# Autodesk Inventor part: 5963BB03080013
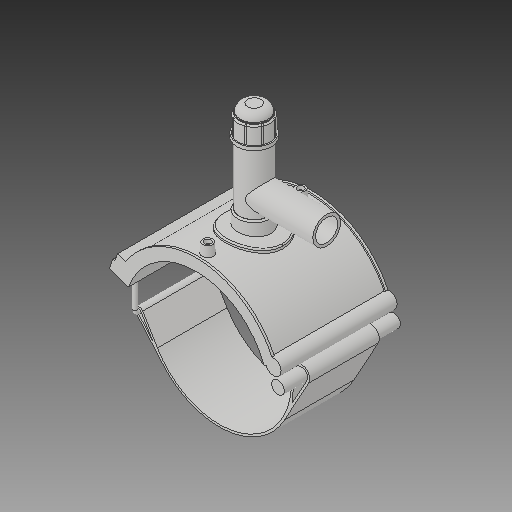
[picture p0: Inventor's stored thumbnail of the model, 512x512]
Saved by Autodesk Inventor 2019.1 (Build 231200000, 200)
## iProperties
Created: 2017-07
Part Number: 5963BB03080013
Material: Generic
Description: PLASSON TAPPING SADDLE 8''IPS x 1 1/4''IPS
Document SubType Name: Modeling
Designer: KIM
Mass: 1712.7 g
Surface Area: 2671.49 cm^2
Volume: 1712.7 cm^3
Density: 1 g/cm^3
Appearance: Default
Author: KIM
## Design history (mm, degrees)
derived "5963B.ipt"
feature "Solid1::5963B.ipt"
feature "Solid2::5963B.ipt"
feature "Solid4::5963B.ipt"
feature "Solid5::5963B.ipt"
tag "TaggingFeature1" dims "d0" = 218.7
body "Solid1"
body "Solid2"
other parameters: "d2" = 269.748, "d3" = 54.675, "d4" = 176.022, "d5" = 0, "d6" = 0.1, "d8" = 0, "d19" = 6, "d20" = 6, "d21" = 105.6132, "d23" = 0, "d24" = 52.8066, "d26" = 0, "d29" = 3, "d30" = 72.9, "d31" = 6, "d32" = 0, "d33" = 0, "d34" = 0.6, "d40" = 129.64536, "d41" = 87.48, "d43" = 0, "d45" = 0, "d47" = 230.2722, "d70" = 15, "d72" = 0, "d73" = 6, "d75" = 5, "d76" = 0, "d77" = 10.935, "d78" = 139.35, "d79" = 15, "d80" = 70.4088, "d82" = 5 deg, "d84" = 4, "d85" = 14, "d86" = 0, "d87" = 3, "d88" = 0, "d89" = 1, "d90" = 1, "d91" = 140.8176, "d92" = 0, "d93" = 0.5, "d94" = 115.10526, "d96" = 254.30436, "d97" = 3.52044, "d98" = 0, "d102" = 2.187, "d120" = 140 deg, "d121" = 24.228, "d122" = 20 deg, "d123" = 498.636, "d124" = 149.5908, "d126" = 0, "d143" = 225.261, "d145" = 23.55231, "d149" = 3.2805, "d150" = 25.90754, "d153" = 176.022, "d154" = 0, "d156" = 124.659, "d157" = 160 deg, "d159" = 6.1236, "d161" = 3.2805, "d162" = 105.6132, "d163" = 0, "d164" = 109.35, "d167" = 21.87, "d168" = 121.61854, "d170" = 3.2805, "d172" = 0, "d173" = 1, "d175" = 109.35, "d176" = 20 deg, "d177" = 15.309, "d178" = 30.618, "d180" = 0, "d183" = 12.2472, "d184" = 12.2472, "d185" = 57.20715, "d186" = 57.20715, "d187" = 124.659, "d188" = 9.1854, "d189" = 15.309, "d190" = 0, "d191" = 186.9885, "d193" = 6.1236, "d194" = 6.16077, "d195" = 90 deg, "d197" = 0, "d199" = 0, "d200" = 15.309, "d202" = 0, "d203" = 177.038, "d204" = 49.8636, "d205" = 36.7416, "d206" = 44.6148, "d207" = 132.7785, "d208" = 138.08964, "d209" = 164.64534, "d210" = 45.13968, "d211" = 52.488, "d212" = 41.9904, "d213" = 39.5766, "d216" = 0, "d217" = 21.87, "d218" = 10.935, "d219" = 2.187, "d222" = 218.7, "d224" = 0, "d230" = 2.187, "d233" = 6, "d236" = 89.916, "d237" = 52.8066, "d238" = 6.02433, "d240" = 52.8066, "d241" = 52.8066, "d242" = 52.8066, "d243" = 6, "d244" = 52.8066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
